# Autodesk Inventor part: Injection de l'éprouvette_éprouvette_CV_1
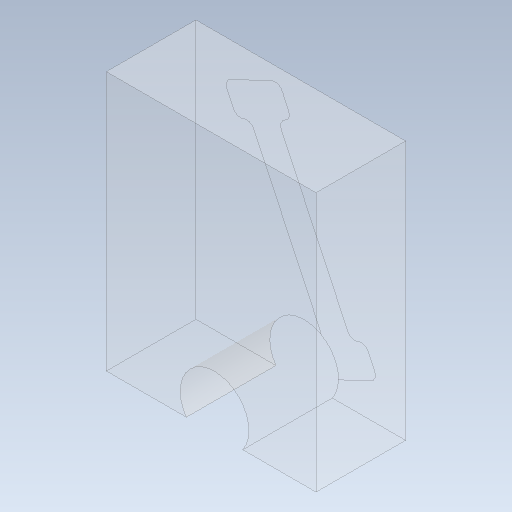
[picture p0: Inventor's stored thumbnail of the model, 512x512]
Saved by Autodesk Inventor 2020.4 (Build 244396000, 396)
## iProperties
Created: 2021-10
Part Number: Injection de l'éprouvette_éprouvette_CV_1
Material: Générique
Document SubType Name: Modeling
Designer: mel
Density: 1 g/cm^3
Appearance: Par défaut
Author: mel
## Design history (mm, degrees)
node "Injection de l'éprouvette_éprouvette_CV_Base"
feature "Sculpter4"
feature "Solide2::Injection de l'éprouvette_éprouvette_CV_Base"
tag "FonctionRepérage2"
node "Solide2"
feature "Injection de l'éprouvette_éprouvette_CV_Base_Corps"
feature "Surface4"
body "Srf4"
